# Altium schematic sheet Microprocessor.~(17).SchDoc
size A4; SheetNumber: 1; SheetTotal: 1
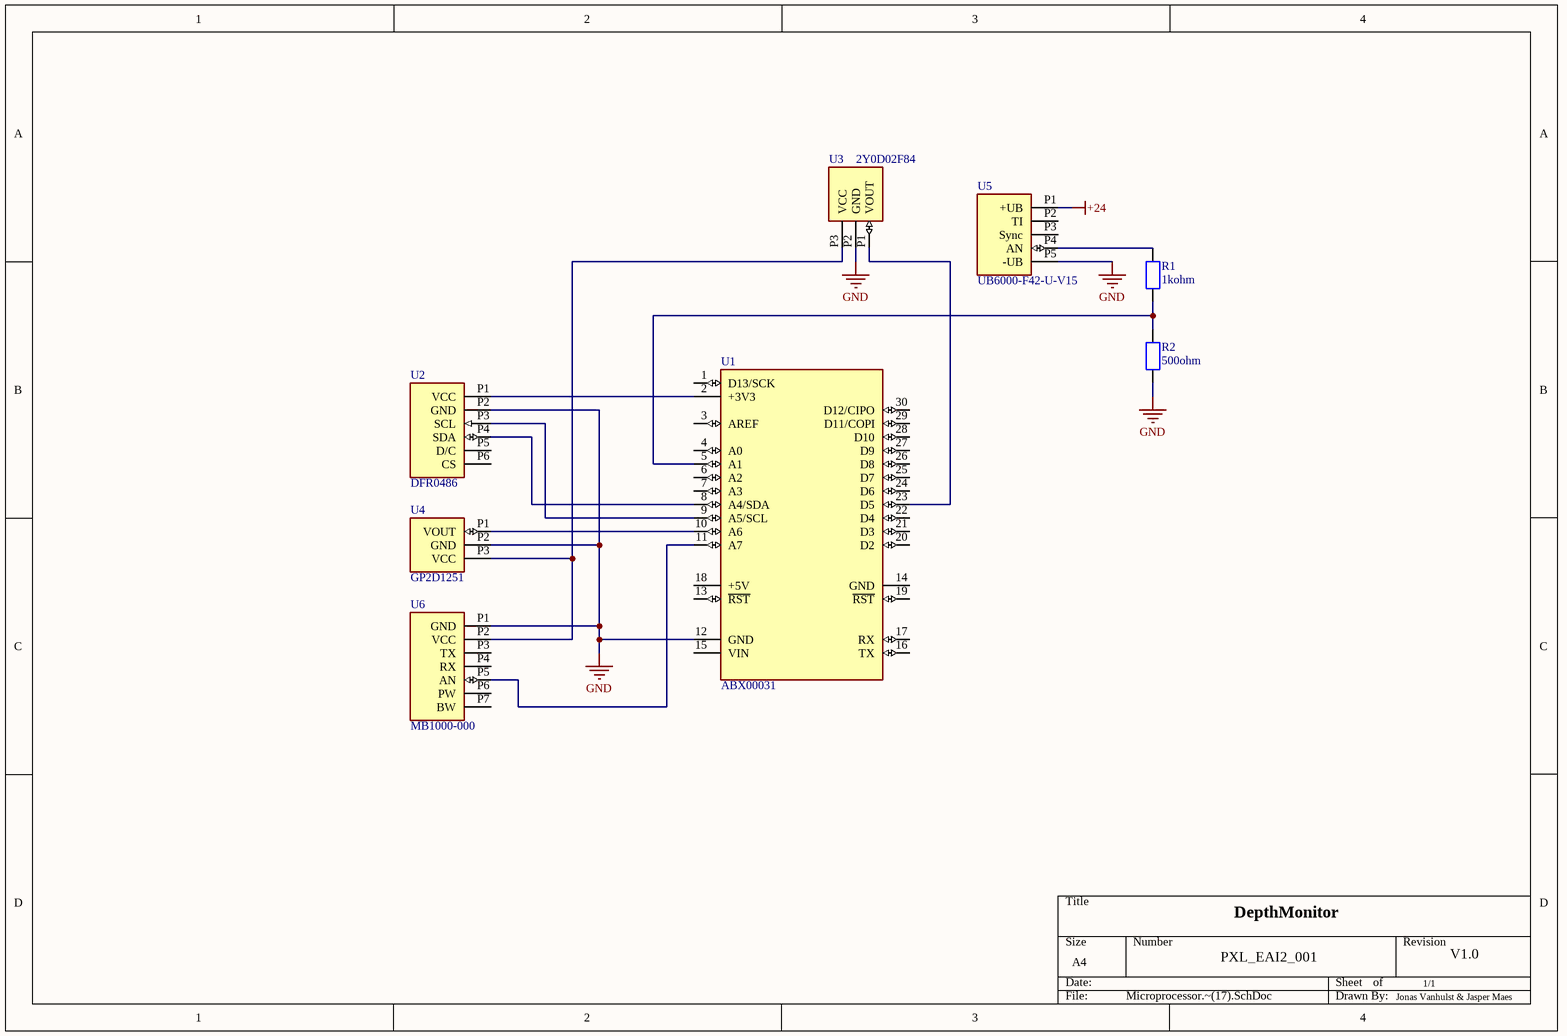
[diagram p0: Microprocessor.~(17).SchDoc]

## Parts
R1  1kohm  [Weerstand 1M ohm]
R2  500ohm  [Weerstand 1M ohm]
U1  ABX00031  [MODULE_ABX00030]
U2  DFR0486  [GP2DXX]
U3  2Y0D02F84  [GP2DXX]
U4  GP2D1251  [GP2DXX]
U5  UB6000-F42-U-V15  [GP2DXX]
U6  MB1000-000  [GP2DXX]

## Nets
+24: U5.P1(+UB)
GND: R2.2 U1.12(GND) U2.P2(GND) U3.P2(GND) U4.P2(GND) U5.P5(-UB) U6.P1(GND)
NetR1_1: R1.1 U5.P4(AN)
NetR1_2: R1.2 R2.1 U1.5(A1)
NetU1_2: U1.2(+3V3) U2.P1(VCC)
NetU1_8: U1.8(A4/SDA) U2.P4(SDA)
NetU1_9: U1.9(A5/SCL) U2.P3(SCL)
NetU1_10: U1.10(A6) U4.P1(VOUT)
NetU1_11: U1.11(A7) U6.P5(AN)
NetU1_23: U1.23(D5) U3.P1(VOUT)
NetU3_P3: U3.P3(VCC) U4.P3(VCC) U6.P2(VCC)

Not connected (* = marked no-connect by the designer): U1 1(D13/SCK) 3(AREF) 4(A0) 6(A2) 7(A3) 13(~{RST}) 14(GND) 15(VIN) 16(TX) 17(RX) 18(+5V) 19(~{RST}) 20(D2) 21(D3) 22(D4) 24(D6) 25(D7) 26(D8) 27(D9) 28(D10) 29(D11/COPI) 30(D12/CIPO); U2 P5(D/C) P6(CS); U5 P2(TI) P3(Sync); U6 P3(TX) P4(RX) P6(PW) P7(BW)

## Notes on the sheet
- DepthMonitor
- PXL_EAI2_001
- 1/1
- V1.0
- Jonas Vanhulst & Jasper Maes

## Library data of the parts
R1 = Weerstand 1 kohm: Manufacturer: Vishay Dale; Part Number: CRCW0805100RFKEA
R2 = Weerstand 500 ohm: Manufacturer: Vishay Dale; Part Number: CRCW0805100RFKEA
U1 = ABX00031: Arduino Nano 33 BLE; MP: ABX00030
U2 = DFR0486: 0.96" 128x64 OLED(V1.0) display DFROBOT; MP: GP2D120; MF: Sharp
U3 = 2Y0D02F84: SENSOR OPTICAL ANALOG; MP: GP2D120; MF: Sharp
U4 = GP2D1251: SENSOR OPTICAL ANALOG; MP: GP2D120; MF: Sharp
U5 = UB6000-F42-U-V15: Ultrasonic sensor; MP: GP2D120; MF: Sharp
U6 = MB1000-000: Analog ultrasonic sensor; MP: GP2D120; MF: Sharp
